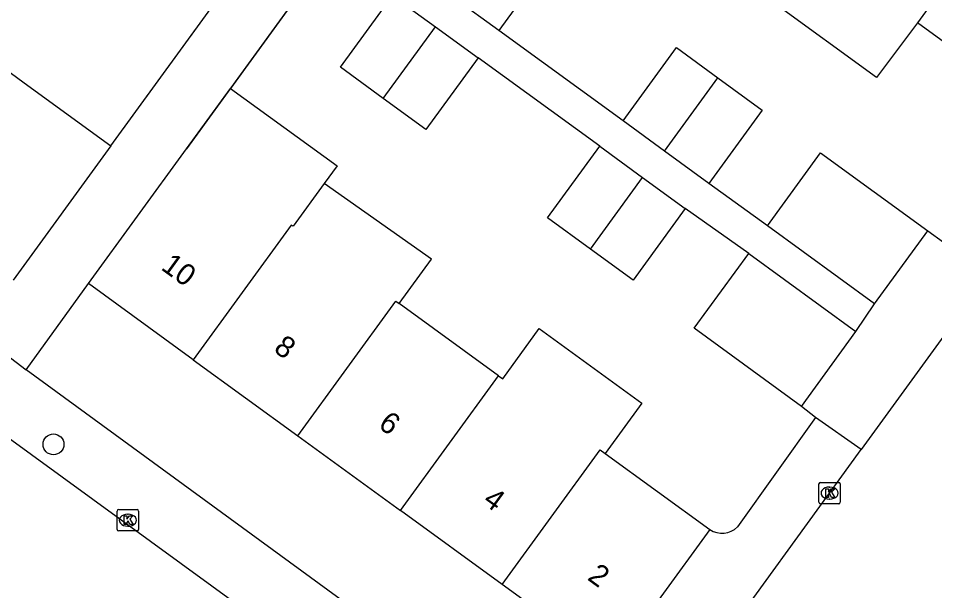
# Model space of a CAD drawing. Extents: x 159675 to 160530, y 382179 to 382901.
# Drawn here: x 160224.11 to 160266.94, y 382561.72 to 382588.46 of the extents above; entities that cross this region are included whole.
import ezdxf

# ---------------------------------------------------------------- set-up
doc = ezdxf.new("R2010")
doc.units = 0
for name, color, linetype in [('IMGEO_Boom', 7, 'Continuous'), ('IMGEO_Kolk', 7, 'Continuous'), ('IMGEO_Muur', 7, 'Continuous'), ('IMGEO_Pand', 7, 'Continuous'), ('IMGEO_Pand_nummerreeks', 7, 'Continuous'), ('IMGEO_Rijbaan_lokaal_gesloten', 7, 'Continuous'), ('IMGEO_Rijbaan_lokaal_open', 7, 'Continuous'), ('IMGEO_Voetpad_open', 7, 'Continuous')]:
    doc.layers.add(name, color=color, linetype=linetype)

msp = doc.modelspace()

# ---------------------------------------------------------------- linework, layer by layer
at = {"layer": 'IMGEO_Boom'}
msp.add_circle((160225.751, 382568.553), 0.489, dxfattribs=at)
at = {"layer": 'IMGEO_Kolk'}
for p, q in [((160261.528, 382565.849), (160261.528, 382566.701)), ((160261.603, 382566.775), (160262.455, 382566.775)), ((160262.529, 382566.701), (160262.529, 382565.849)), ((160262.016, 382566.555), (160262.041, 382566.555)), ((160262.455, 382565.775), (160261.603, 382565.775)), ((160262.039, 382565.995), (160262.014, 382565.995)), ((160228.728, 382564.582), (160228.728, 382565.434)), ((160228.803, 382565.508), (160229.655, 382565.508)), ((160229.729, 382565.434), (160229.729, 382564.582)), ((160229.216, 382565.288), (160229.241, 382565.288)), ((160229.655, 382564.508), (160228.803, 382564.508)), ((160229.239, 382564.728), (160229.214, 382564.728))]:
    msp.add_line(p, q, dxfattribs=at)
for points in [[(160261.528, 382565.849), (160261.528, 382566.701)], [(160261.603, 382566.775), (160262.455, 382566.775)], [(160262.529, 382566.701), (160262.529, 382565.849)], [(160261.849, 382566.475), (160261.972, 382566.475), (160261.972, 382566.324), (160262.102, 382566.475), (160262.266, 382566.475), (160262.12, 382566.324), (160262.273, 382566.075), (160262.121, 382566.075), (160262.036, 382566.239), (160261.972, 382566.172), (160261.972, 382566.075), (160261.849, 382566.075), (160261.849, 382566.475)], [(160262.455, 382565.775), (160261.603, 382565.775)], [(160228.728, 382564.582), (160228.728, 382565.434)], [(160228.803, 382565.508), (160229.655, 382565.508)], [(160229.729, 382565.434), (160229.729, 382564.582)], [(160229.049, 382565.208), (160229.172, 382565.208), (160229.172, 382565.057), (160229.302, 382565.208), (160229.466, 382565.208), (160229.32, 382565.057), (160229.473, 382564.808), (160229.321, 382564.808), (160229.236, 382564.972), (160229.172, 382564.905), (160229.172, 382564.808), (160229.049, 382564.808), (160229.049, 382565.208)], [(160229.655, 382564.508), (160228.803, 382564.508)]]:
    msp.add_lwpolyline(points, dxfattribs=at)
for centre, start, end in [((160261.605, 382566.699), 91.552, 178.448), ((160261.605, 382566.699), 91.552, 178.448), ((160262.453, 382566.699), 1.552, 88.448), ((160262.453, 382566.699), 1.552, 88.448), ((160261.605, 382565.851), 181.552, 268.448), ((160261.605, 382565.851), 181.552, 268.448), ((160262.453, 382565.851), 271.552, 358.448), ((160262.453, 382565.851), 271.552, 358.448), ((160228.805, 382565.432), 91.552, 178.448), ((160228.805, 382565.432), 91.552, 178.448), ((160229.653, 382565.432), 1.552, 88.448), ((160229.653, 382565.432), 1.552, 88.448), ((160228.805, 382564.584), 181.552, 268.448), ((160228.805, 382564.584), 181.552, 268.448), ((160229.653, 382564.584), 271.552, 358.448), ((160229.653, 382564.584), 271.552, 358.448)]:
    msp.add_arc(centre, 0.0765, start, end, dxfattribs=at)
for centre, major_axis, ratio, start_param, end_param in [((160262.015, 382566.275), (-0.387, 0.002), 0.722429, 4.712389, 7.853982), ((160262.04, 382566.275), (-0.39, 0.002), 0.717154, 1.570796, 4.712389), ((160229.215, 382565.008), (-0.387, 0.002), 0.722429, 4.712389, 7.853982), ((160229.24, 382565.008), (-0.39, 0.002), 0.717154, 1.570796, 4.712389)]:
    msp.add_ellipse(centre, major_axis=major_axis, ratio=ratio, start_param=start_param, end_param=end_param, dxfattribs=at)
at = {"layer": 'IMGEO_Muur'}
for points in [[(160228.427, 382582.503), (160245.379, 382605.794)], [(160246.587, 382602.485), (160231.976, 382582.36)]]:
    msp.add_lwpolyline(points, dxfattribs=at)
msp.add_arc((160257.004, 382565.426), 1.028, 236.1173, 314.6464, dxfattribs=at)
at = {"layer": 'IMGEO_Pand'}
for points in [[(160270.68, 382594.506), (160266.13, 382588.256)], [(160246.995, 382592.823), (160249.066, 382591.315), (160246.573, 382587.891)], [(160266.13, 382588.256), (160264.22, 382585.689), (160259.378, 382589.214), (160261.261, 382591.801)], [(160241.166, 382584.714), (160239.162, 382586.173), (160241.603, 382589.525)], [(160241.603, 382589.525), (160243.605, 382588.067)], [(160246.573, 382587.891), (160244.502, 382589.399)], [(160241.166, 382584.714), (160243.605, 382588.067)], [(160243.605, 382588.067), (160245.602, 382586.613)], [(160271.056, 382584.669), (160266.13, 382588.256)], [(160252.375, 382583.666), (160254.868, 382587.09), (160256.804, 382585.68)], [(160245.602, 382586.613), (160243.161, 382583.261), (160241.166, 382584.714)], [(160223.426, 382586.14), (160224.383, 382585.444), (160228.427, 382582.503)], [(160254.311, 382582.256), (160256.804, 382585.68)], [(160256.804, 382585.68), (160258.875, 382584.172), (160256.382, 382580.748)], [(160227.395, 382576.062), (160231.976, 382582.36), (160234.032, 382585.187)], [(160234.032, 382585.187), (160239.007, 382581.569), (160238.409, 382580.747)], [(160254.311, 382582.256), (160252.375, 382583.666)], [(160228.427, 382582.503), (160223.859, 382576.224)], [(160250.847, 382577.673), (160248.843, 382579.132), (160251.284, 382582.484)], [(160251.284, 382582.484), (160253.286, 382581.026)], [(160256.382, 382580.748), (160254.311, 382582.256)], [(160259.119, 382578.762), (160261.605, 382582.176), (160266.618, 382578.526)], [(160238.409, 382580.747), (160236.951, 382578.742), (160236.868, 382578.802), (160232.288, 382572.503)], [(160241.909, 382575.136), (160243.42, 382577.213), (160238.409, 382580.747)], [(160250.847, 382577.673), (160253.286, 382581.026)], [(160253.286, 382581.026), (160255.283, 382579.572)], [(160255.283, 382579.572), (160252.842, 382576.22), (160250.847, 382577.673)], [(160264.132, 382575.112), (160259.119, 382578.762)], [(160264.132, 382575.112), (160266.618, 382578.526)], [(160260.709, 382570.329), (160255.701, 382573.975), (160258.248, 382577.474)], [(160258.248, 382577.474), (160263.256, 382573.828)], [(160232.288, 382572.503), (160227.395, 382576.062)], [(160237.179, 382568.945), (160241.76, 382575.244), (160241.909, 382575.136)], [(160246.549, 382571.761), (160241.909, 382575.136)], [(160246.549, 382571.761), (160246.751, 382571.614), (160248.457, 382573.961), (160253.249, 382570.477), (160251.542, 382568.129)], [(160260.709, 382570.329), (160263.256, 382573.828)], [(160232.288, 382572.503), (160237.179, 382568.945)], [(160241.969, 382565.462), (160246.549, 382571.761)], [(160237.179, 382568.945), (160241.969, 382565.462)], [(160246.728, 382562), (160251.309, 382568.299), (160251.542, 382568.129)], [(160251.542, 382568.129), (160256.431, 382564.573)], [(160246.728, 382562), (160241.969, 382565.462)], [(160256.431, 382564.573), (160251.85, 382558.275)], [(160251.85, 382558.275), (160246.728, 382562)]]:
    msp.add_lwpolyline(points, dxfattribs=at)
at = {"layer": 'IMGEO_Rijbaan_lokaal_gesloten'}
for points in [[(160269.482, 382576.534), (160263.507, 382568.309)], [(160253.079, 382553.951), (160253.466, 382554.485), (160263.507, 382568.309)]]:
    msp.add_lwpolyline(points, dxfattribs=at)
at = {"layer": 'IMGEO_Rijbaan_lokaal_open'}
msp.add_lwpolyline([(160245.716, 382552.786), (160140.763, 382629.192), (160140.555, 382629.351)], dxfattribs=at)
at = {"layer": 'IMGEO_Voetpad_open'}
for points in [[(160228.427, 382582.503), (160236.364, 382593.408)], [(160238.707, 382591.628), (160234.032, 382585.187)], [(160252.375, 382583.666), (160246.573, 382587.891)], [(160251.284, 382582.484), (160245.602, 382586.613)], [(160259.119, 382578.762), (160256.382, 382580.748)], [(160258.248, 382577.474), (160255.283, 382579.572)], [(160266.618, 382578.526), (160267.346, 382578.004)], [(160224.48, 382572.038), (160227.395, 382576.062)], [(160263.256, 382573.828), (160264.132, 382575.112)], [(160222.117, 382573.829), (160224.48, 382572.038)], [(160246.891, 382555.658), (160224.48, 382572.038)], [(160261.372, 382569.812), (160260.709, 382570.329)], [(160261.372, 382569.812), (160257.726, 382564.695)], [(160263.507, 382568.309), (160261.372, 382569.812)]]:
    msp.add_lwpolyline(points, dxfattribs=at)
msp.add_arc((160257.004, 382565.426), 1.028, 236.1173, 314.6464, dxfattribs=at)

# ---------------------------------------------------------------- texts
at = {"layer": 'IMGEO_Pand_nummerreeks'}
for s, p in [('10', (160230.73, 382576.753)), ('8', (160235.994, 382572.924)), ('6', (160240.881, 382569.369)), ('4', (160245.772, 382565.811)), ('2', (160250.662, 382562.256))]:
    msp.add_text(s, height=1, rotation=323.9724, dxfattribs=at).set_placement(p)

doc.saveas('drawing.dxf')
